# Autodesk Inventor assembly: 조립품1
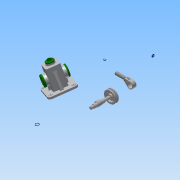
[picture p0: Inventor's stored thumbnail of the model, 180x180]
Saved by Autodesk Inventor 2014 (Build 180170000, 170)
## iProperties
Created: 2015-12
Part Number: 조립품1
Document SubType Name: Assembly
Designer: Administrator
Author: Administrator
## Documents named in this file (19)
- D:\451225V1016\조립품1.iam
- D:\451225V1016\고정핀.ipt
- D:\451225V1016\뒤커버.ipt
- D:\451225V1016\링크.ipt
- D:\451225V1016\멈춤링 6 x 5.ipt
- D:\451225V1016\멈춤링 15 x 1.ipt
- D:\451225V1016\베어링 15 x 35 x 11.ipt
- D:\451225V1016\본체.ipt
- D:\451225V1016\볼트 M3 x 8.ipt
- D:\451225V1016\볼트 M4 x 10.ipt
- D:\451225V1016\볼트 M6 x 12.ipt
- D:\451225V1016\상부부시.ipt
- D:\451225V1016\슬라이드바.ipt
- D:\451225V1016\앞커버.ipt
- D:\451225V1016\오일실 15 25 7.ipt
- D:\451225V1016\와셔.ipt
- D:\451225V1016\키 5 x 5 x 14.ipt
- D:\451225V1016\편심축.ipt
- D:\451225V1016\V-벨트풀리.ipt
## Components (15 placed, 5 different names)
1. 고정핀:1
2. V-벨트풀리:1
3. ISO 4018 M6 x 12:2
4. ISO 4762 M4 x 10:1
5. ISO 4762 M4 x 10:2
6. ISO 4762 M4 x 10:3
7. ISO 4762 M4 x 10:4
8. ISO 4762 M4 x 10:5
9. ISO 4762 M4 x 10:6
10. ISO 4762 M4 x 10:7
11. ISO 4762 M4 x 10:8
12. ISO 4762 M3 x 8:2
13. ISO 4762 M3 x 8:3
14. ISO 4762 M3 x 8:4
15. ISO 4762 M3 x 8:5
